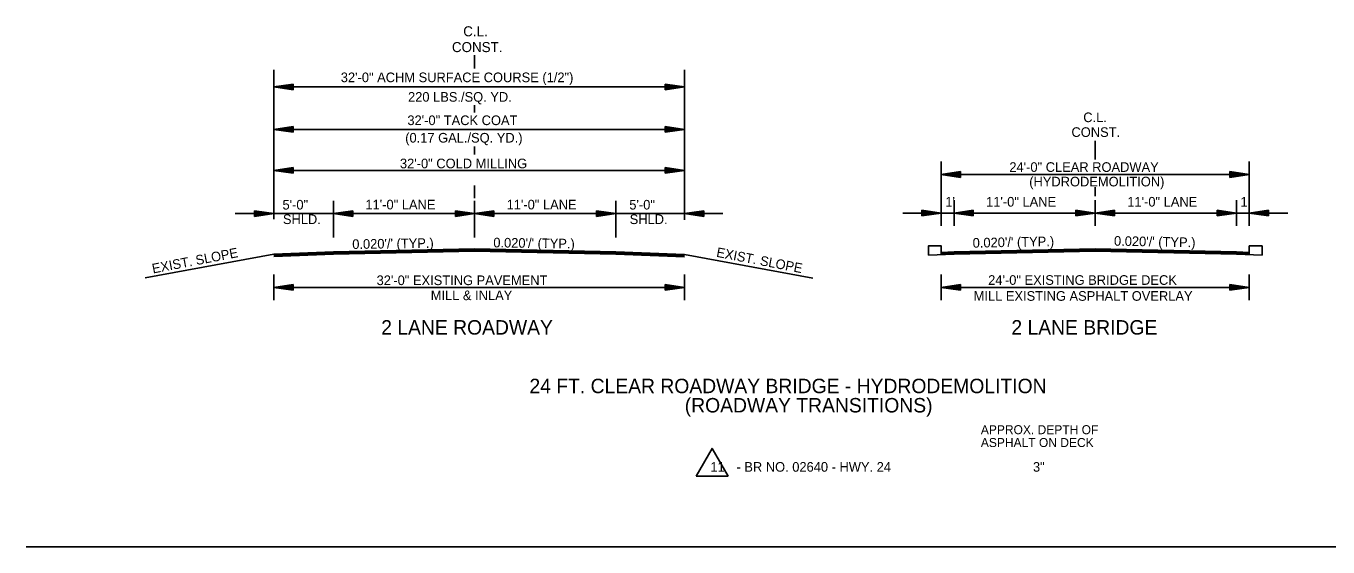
# Model space of a CAD drawing. Extents: x 549600 to 1930787, y -1955432 to 596640.
# Drawn here: x 551009 to 552023, y -1949914 to -1949509 of the extents above; entities that cross this region are included whole.
import ezdxf

# ---------------------------------------------------------------- set-up
doc = ezdxf.new("R2010")
doc.units = 0
for name, color, linetype in [('R_Border', 7, 'Continuous'), ('R_Border Notes', 7, 'Continuous'), ('S_AREA_CALC', 7, 'Continuous')]:
    doc.layers.add(name, color=color, linetype=linetype)

# ---------------------------------------------------------------- blocks, each defined once
blk = doc.blocks.new('ARROW')
at = {"layer": 'S_AREA_CALC'}
for p, q in [((-2, 0.3), (0, 0)), ((-2, 0.3), (-2, -0.3)), ((-2, 0.25), (-0.334, 0)), ((-2, 0.199), (-0.678, 0)), ((-2, 0.149), (-1.011, 0)), ((-2, 0.097), (-1.35, 0)), ((-2, 0.047), (-1.684, 0)), ((-2, -0.3), (0, 0)), ((-2, -0.098), (-1.35, 0)), ((-2, -0.199), (-0.678, 0)), ((-2, -0.25), (-0.334, 0)), ((-2, -0.149), (-1.011, 0)), ((-2, -0.047), (-1.684, 0))]:
    blk.add_line(p, q, dxfattribs=at)

msp = doc.modelspace()

# ---------------------------------------------------------------- linework, layer by layer
at = {"layer": 'R_Border'}
for p, q in [((551842, -1949598), (551842, -1949612.5)), ((551722, -1949614.2), (551722, -1949664.2)), ((551962, -1949614.2), (551962, -1949664.2)), ((551722, -1949624.2), (551962, -1949624.2)), ((551842, -1949634.2), (551842, -1949641.2)), ((551732, -1949644.2), (551732, -1949664.2)), ((551842, -1949644.2), (551842, -1949664.2)), ((551952, -1949644.2), (551952, -1949664.2)), ((551202, -1949654.6), (551172, -1949654.6)), ((551552, -1949654.6), (551522, -1949654.6)), ((551692, -1949654.2), (551992, -1949654.2)), ((551248.5, -1949684.4), (551202, -1949686.3)), ((551248.5, -1949684.7), (551202, -1949686.6)), ((551248.5, -1949685), (551202, -1949686.9)), ((551248.5, -1949685.3), (551202, -1949687.2)), ((551248.5, -1949685.6), (551202, -1949687.5)), ((551248.5, -1949685.9), (551202, -1949687.8)), ((551248.5, -1949686.1), (551202, -1949688)), ((551468.5, -1949684.4), (551522, -1949686.6)), ((551468.5, -1949684.7), (551522, -1949686.9)), ((551468.5, -1949685), (551522, -1949687.2)), ((551468.5, -1949685.3), (551522, -1949687.5)), ((551468.5, -1949685.6), (551522, -1949687.8)), ((551468.5, -1949685.9), (551522, -1949688.1)), ((551468.5, -1949686.1), (551522, -1949688.2)), ((551722, -1949702.1), (551722, -1949722.1)), ((551962, -1949702.1), (551962, -1949722.1)), ((551722, -1949712.1), (551962, -1949712.1)), ((551531.1, -1949858.9), (551555.9, -1949858.9)), ((551009, -1949914), (552070.2, -1949914))]:
    msp.add_line(p, q, dxfattribs=at)
for points in [[(551722, -1949686.3), (551722, -1949679.8), (551712, -1949679.8), (551712, -1949687)], [(551962, -1949687), (551962, -1949679.8), (551972, -1949679.8), (551972, -1949687)], [(551712, -1949687), (551732, -1949686.2), (551842, -1949684), (551952, -1949686.2), (551972, -1949687)], [(551722, -1949684.8), (551732, -1949684.4), (551842, -1949682.2), (551952, -1949684.4), (551962, -1949684.8)], [(551722, -1949685.1), (551732, -1949684.7), (551842, -1949682.5), (551952, -1949684.7), (551962, -1949685.1)], [(551722, -1949685.4), (551732, -1949685), (551842, -1949682.8), (551952, -1949685), (551962, -1949685.4)], [(551722, -1949685.7), (551732, -1949685.3), (551842, -1949683.1), (551952, -1949685.3), (551962, -1949685.7)], [(551722, -1949686), (551732, -1949685.6), (551842, -1949683.4), (551952, -1949685.6), (551962, -1949686)], [(551722, -1949686.3), (551732, -1949685.9), (551842, -1949683.7), (551952, -1949685.9), (551962, -1949686.3)], [(551555.9, -1949858.9), (551543.5, -1949837.4), (551531.1, -1949858.9)]]:
    msp.add_lwpolyline(points, dxfattribs=at)
at = {"layer": 'S_AREA_CALC'}
for p, q in [((551358.5, -1949541.7), (551358.5, -1949531.3)), ((551202, -1949659.1), (551202, -1949542.8)), ((551522, -1949659.6), (551522, -1949542.8)), ((551217, -1949553.9), (551202, -1949556.1)), ((551202, -1949556.1), (551522, -1949556.1)), ((551217, -1949558.4), (551202, -1949556.1)), ((551217, -1949554.3), (551204.5, -1949556.1)), ((551217, -1949558), (551204.5, -1949556.1)), ((551217, -1949554.6), (551207.1, -1949556.1)), ((551217, -1949557.6), (551207.1, -1949556.1)), ((551217, -1949555), (551209.6, -1949556.1)), ((551217, -1949557.3), (551209.6, -1949556.1)), ((551217, -1949555.4), (551212.1, -1949556.1)), ((551217, -1949556.9), (551212.1, -1949556.1)), ((551217, -1949555.8), (551214.6, -1949556.1)), ((551217, -1949556.5), (551214.6, -1949556.1)), ((551217, -1949558.4), (551217, -1949553.9)), ((551507, -1949553.9), (551522, -1949556.1)), ((551507, -1949553.9), (551507, -1949558.4)), ((551507, -1949554.3), (551519.5, -1949556.1)), ((551507, -1949554.6), (551516.9, -1949556.1)), ((551507, -1949555), (551514.4, -1949556.1)), ((551507, -1949555.4), (551511.9, -1949556.1)), ((551507, -1949555.8), (551509.4, -1949556.1)), ((551507, -1949558.4), (551522, -1949556.1)), ((551507, -1949556.9), (551511.9, -1949556.1)), ((551507, -1949557.6), (551516.9, -1949556.1)), ((551507, -1949558), (551519.5, -1949556.1)), ((551507, -1949557.3), (551514.4, -1949556.1)), ((551507, -1949556.5), (551509.4, -1949556.1)), ((551358.5, -1949575.9), (551358.5, -1949570.3)), ((551217, -1949586.9), (551202, -1949589.1)), ((551202, -1949589.1), (551522, -1949589.1)), ((551217, -1949591.4), (551202, -1949589.1)), ((551217, -1949587.2), (551204.5, -1949589.1)), ((551217, -1949591), (551204.5, -1949589.1)), ((551217, -1949587.6), (551207.1, -1949589.1)), ((551217, -1949590.6), (551207.1, -1949589.1)), ((551217, -1949588), (551209.6, -1949589.1)), ((551217, -1949590.2), (551209.6, -1949589.1)), ((551217, -1949588.4), (551212.1, -1949589.1)), ((551217, -1949589.8), (551212.1, -1949589.1)), ((551217, -1949588.8), (551214.6, -1949589.1)), ((551217, -1949589.5), (551214.6, -1949589.1)), ((551217, -1949591.4), (551217, -1949586.9)), ((551507, -1949586.9), (551522, -1949589.1)), ((551507, -1949586.9), (551507, -1949591.4)), ((551507, -1949587.2), (551519.5, -1949589.1)), ((551507, -1949587.6), (551516.9, -1949589.1)), ((551507, -1949588), (551514.4, -1949589.1)), ((551507, -1949588.4), (551511.9, -1949589.1)), ((551507, -1949588.8), (551509.4, -1949589.1)), ((551507, -1949591.4), (551522, -1949589.1)), ((551507, -1949589.8), (551511.9, -1949589.1)), ((551507, -1949590.6), (551516.9, -1949589.1)), ((551507, -1949591), (551519.5, -1949589.1)), ((551507, -1949590.2), (551514.4, -1949589.1)), ((551507, -1949589.5), (551509.4, -1949589.1)), ((551358.5, -1949608.8), (551358.5, -1949602.4)), ((551217, -1949618.8), (551202, -1949621.1)), ((551217, -1949619.2), (551204.5, -1949621.1)), ((551217, -1949619.6), (551207.1, -1949621.1)), ((551217, -1949620), (551209.6, -1949621.1)), ((551217, -1949620.3), (551212.1, -1949621.1)), ((551217, -1949620.7), (551214.6, -1949621.1)), ((551217, -1949623.3), (551217, -1949618.8)), ((551507, -1949618.8), (551522, -1949621.1)), ((551507, -1949618.8), (551507, -1949623.3)), ((551507, -1949619.2), (551519.5, -1949621.1)), ((551507, -1949619.6), (551516.9, -1949621.1)), ((551507, -1949620), (551514.4, -1949621.1)), ((551507, -1949620.4), (551511.9, -1949621.1)), ((551507, -1949620.7), (551509.4, -1949621.1)), ((551202, -1949621.1), (551522, -1949621.1)), ((551217, -1949623.3), (551202, -1949621.1)), ((551217, -1949623), (551204.5, -1949621.1)), ((551217, -1949622.6), (551207.1, -1949621.1)), ((551217, -1949622.2), (551209.6, -1949621.1)), ((551217, -1949621.8), (551212.1, -1949621.1)), ((551217, -1949621.4), (551214.6, -1949621.1)), ((551507, -1949623.3), (551522, -1949621.1)), ((551507, -1949621.8), (551511.9, -1949621.1)), ((551507, -1949622.6), (551516.9, -1949621.1)), ((551507, -1949623), (551519.5, -1949621.1)), ((551507, -1949622.2), (551514.4, -1949621.1)), ((551507, -1949621.4), (551509.4, -1949621.1)), ((551358.5, -1949642.6), (551358.5, -1949632.7)), ((551248.5, -1949673.3), (551248.5, -1949644.7)), ((551358.5, -1949673.3), (551358.5, -1949644.7)), ((551468.5, -1949673.3), (551468.5, -1949644.7)), ((551187, -1949652.4), (551202, -1949654.6)), ((551187, -1949652.4), (551187, -1949656.9)), ((551187, -1949652.7), (551199.5, -1949654.6)), ((551187, -1949653.1), (551196.9, -1949654.6)), ((551187, -1949653.5), (551194.4, -1949654.6)), ((551187, -1949653.9), (551191.9, -1949654.6)), ((551187, -1949654.3), (551189.4, -1949654.6)), ((551187, -1949656.9), (551202, -1949654.6)), ((551187, -1949655.4), (551191.9, -1949654.6)), ((551187, -1949656.1), (551196.9, -1949654.6)), ((551187, -1949656.5), (551199.5, -1949654.6)), ((551187, -1949655.7), (551194.4, -1949654.6)), ((551187, -1949655), (551189.4, -1949654.6)), ((551248.5, -1949654.6), (551202, -1949654.6)), ((551263.5, -1949652.4), (551248.5, -1949654.6)), ((551263.5, -1949656.9), (551248.5, -1949654.6)), ((551248.5, -1949654.6), (551358.5, -1949654.6)), ((551263.5, -1949652.7), (551251, -1949654.6)), ((551263.5, -1949656.5), (551251, -1949654.6)), ((551263.5, -1949653.1), (551253.6, -1949654.6)), ((551263.5, -1949656.1), (551253.6, -1949654.6)), ((551263.5, -1949653.5), (551256.1, -1949654.6)), ((551263.5, -1949655.7), (551256.1, -1949654.6)), ((551263.5, -1949653.9), (551258.6, -1949654.6)), ((551263.5, -1949655.3), (551258.6, -1949654.6)), ((551263.5, -1949654.3), (551261.1, -1949654.6)), ((551263.5, -1949655), (551261.1, -1949654.6)), ((551263.5, -1949656.9), (551263.5, -1949652.4)), ((551343.5, -1949652.4), (551358.5, -1949654.6)), ((551343.5, -1949652.4), (551343.5, -1949656.9)), ((551343.5, -1949652.7), (551356, -1949654.6)), ((551343.5, -1949653.1), (551353.4, -1949654.6)), ((551343.5, -1949653.5), (551350.9, -1949654.6)), ((551343.5, -1949653.9), (551348.3, -1949654.6)), ((551343.5, -1949654.3), (551345.8, -1949654.6)), ((551343.5, -1949656.9), (551358.5, -1949654.6)), ((551343.5, -1949655.4), (551348.3, -1949654.6)), ((551343.5, -1949656.1), (551353.4, -1949654.6)), ((551343.5, -1949656.5), (551356, -1949654.6)), ((551343.5, -1949655.7), (551350.9, -1949654.6)), ((551343.5, -1949655), (551345.8, -1949654.6)), ((551373.5, -1949652.4), (551358.5, -1949654.6)), ((551468.5, -1949654.6), (551358.5, -1949654.6)), ((551373.5, -1949656.9), (551358.5, -1949654.6)), ((551373.5, -1949652.7), (551361, -1949654.6)), ((551373.5, -1949656.5), (551361, -1949654.6)), ((551373.5, -1949653.1), (551363.6, -1949654.6)), ((551373.5, -1949656.1), (551363.6, -1949654.6)), ((551373.5, -1949653.5), (551366.1, -1949654.6)), ((551373.5, -1949655.7), (551366.1, -1949654.6)), ((551373.5, -1949653.9), (551368.6, -1949654.6)), ((551373.5, -1949655.4), (551368.6, -1949654.6)), ((551373.5, -1949654.3), (551371.1, -1949654.6)), ((551373.5, -1949655), (551371.1, -1949654.6)), ((551373.5, -1949652.4), (551373.5, -1949656.9)), ((551453.5, -1949652.4), (551468.5, -1949654.6)), ((551453.5, -1949656.9), (551453.5, -1949652.4)), ((551453.5, -1949652.7), (551466, -1949654.6)), ((551453.5, -1949653.1), (551463.4, -1949654.6)), ((551453.5, -1949653.5), (551460.9, -1949654.6)), ((551453.5, -1949653.9), (551458.3, -1949654.6)), ((551453.5, -1949654.3), (551455.8, -1949654.6)), ((551453.5, -1949656.9), (551468.5, -1949654.6)), ((551453.5, -1949655.3), (551458.3, -1949654.6)), ((551453.5, -1949656.1), (551463.4, -1949654.6)), ((551453.5, -1949656.5), (551466, -1949654.6)), ((551453.5, -1949655.7), (551460.9, -1949654.6)), ((551453.5, -1949655), (551455.8, -1949654.6)), ((551468.5, -1949654.6), (551522, -1949654.6)), ((551537, -1949652.4), (551522, -1949654.6)), ((551537, -1949656.9), (551522, -1949654.6)), ((551537, -1949652.7), (551524.5, -1949654.6)), ((551537, -1949656.5), (551524.5, -1949654.6)), ((551537, -1949653.1), (551527.1, -1949654.6)), ((551537, -1949656.1), (551527.1, -1949654.6)), ((551537, -1949653.5), (551529.6, -1949654.6)), ((551537, -1949655.7), (551529.6, -1949654.6)), ((551537, -1949653.9), (551532.1, -1949654.6)), ((551537, -1949655.4), (551532.1, -1949654.6)), ((551537, -1949654.3), (551534.6, -1949654.6)), ((551537, -1949655), (551534.6, -1949654.6)), ((551537, -1949652.4), (551537, -1949656.9)), ((551202, -1949686.3), (551101.9, -1949704.7)), ((551358.5, -1949682.2), (551248.5, -1949684.4)), ((551358.5, -1949682.5), (551248.5, -1949684.7)), ((551358.5, -1949682.8), (551248.5, -1949685)), ((551358.5, -1949683.1), (551248.5, -1949685.3)), ((551358.5, -1949683.4), (551248.5, -1949685.6)), ((551358.5, -1949683.7), (551248.5, -1949685.9)), ((551358.5, -1949683.9), (551248.5, -1949686.1)), ((551358.4, -1949683.7), (551468.5, -1949685.9)), ((551358.4, -1949683.9), (551468.5, -1949686.1)), ((551358.5, -1949682.2), (551468.5, -1949684.4)), ((551358.5, -1949682.5), (551468.5, -1949684.7)), ((551358.5, -1949682.8), (551468.5, -1949685)), ((551358.5, -1949683.1), (551468.5, -1949685.3)), ((551358.5, -1949683.4), (551468.5, -1949685.6)), ((551522, -1949686.6), (551622.1, -1949704.9)), ((551202, -1949702.1), (551202, -1949722.1)), ((551522, -1949702.1), (551522, -1949722.1)), ((551217, -1949709.8), (551202, -1949712.1)), ((551202, -1949712.1), (551522, -1949712.1)), ((551217, -1949714.3), (551202, -1949712.1)), ((551217, -1949710.2), (551204.5, -1949712.1)), ((551217, -1949714), (551204.5, -1949712.1)), ((551217, -1949710.6), (551207.1, -1949712.1)), ((551217, -1949713.6), (551207.1, -1949712.1)), ((551217, -1949711), (551209.6, -1949712.1)), ((551217, -1949713.2), (551209.6, -1949712.1)), ((551217, -1949711.3), (551212.1, -1949712.1)), ((551217, -1949712.8), (551212.1, -1949712.1)), ((551217, -1949711.7), (551214.6, -1949712.1)), ((551217, -1949712.4), (551214.6, -1949712.1)), ((551217, -1949714.3), (551217, -1949709.8)), ((551507, -1949709.8), (551522, -1949712.1)), ((551507, -1949709.8), (551507, -1949714.3)), ((551507, -1949710.2), (551519.5, -1949712.1)), ((551507, -1949710.6), (551516.9, -1949712.1)), ((551507, -1949711), (551514.4, -1949712.1)), ((551507, -1949711.4), (551511.9, -1949712.1)), ((551507, -1949711.7), (551509.4, -1949712.1)), ((551507, -1949714.3), (551522, -1949712.1)), ((551507, -1949712.8), (551511.9, -1949712.1)), ((551507, -1949713.6), (551516.9, -1949712.1)), ((551507, -1949714), (551519.5, -1949712.1)), ((551507, -1949713.2), (551514.4, -1949712.1)), ((551507, -1949712.4), (551509.4, -1949712.1))]:
    msp.add_line(p, q, dxfattribs=at)

# ---------------------------------------------------------------- block references
at = {"layer": 'R_Border', "xscale": 7.5, "yscale": 7.5, "rotation": 180}
for p in [(551722, -1949624.2), (551732, -1949654.2), (551842, -1949654.2), (551962, -1949654.2), (551722, -1949712.1)]:
    msp.add_blockref('ARROW', p, dxfattribs=at)
at = {"layer": 'R_Border', "xscale": 7.5, "yscale": 7.5}
for p in [(551962, -1949624.2), (551722, -1949654.2), (551842, -1949654.2), (551952, -1949654.2), (551962, -1949712.1)]:
    msp.add_blockref('ARROW', p, dxfattribs=at)

# ---------------------------------------------------------------- texts
at = {"layer": 'R_Border'}
for s, height, p in [('C.L.', 7.5, (551832.7, -1949583.5)), ('CONST.', 7.5, (551823.5, -1949595)), ('24\'-0" CLEAR ROADWAY', 7.5, (551775.1, -1949622.2)), ('(HYDRODEMOLITION)', 7.5, (551790.6, -1949633.5)), ("1'", 7.5, (551725.2, -1949649.2)), ('11\'-0" LANE', 7.5, (551757, -1949649.2)), ('11\'-0" LANE', 7.5, (551867, -1949649.2)), ("1'", 7.5, (551955.2, -1949649.2)), ('24\'-0" EXISTING BRIDGE DECK', 7.5, (551758.6, -1949710.1)), ('2 LANE ROADWAY', 11.25, (551285.7, -1949748.8)), ('2 LANE BRIDGE', 11.25, (551776.7, -1949748.8)), ('24 FT. CLEAR ROADWAY BRIDGE - HYDRODEMOLITION', 11.25, (551401.2, -1949794.4)), ('(ROADWAY TRANSITIONS)', 11.25, (551522.2, -1949809.4)), ('11', 7.5, (551542.2, -1949855.5)), ('- BR NO. 02640 - HWY. 24', 7.5, (551562.5, -1949855.5)), ('3"', 7.5, (551793.5, -1949855.5))]:
    msp.add_text(s, height=height, dxfattribs=at).set_placement(p)
for rotation, p in [(1.1458, (551746.6, -1949681.2)), (358.8542, (551856.6, -1949679.6))]:
    msp.add_text("0.020'/' (TYP.)", height=7.5, rotation=rotation, dxfattribs=at).set_placement(p)
at = {"layer": 'R_Border Notes'}
for s, p in [('APPROX. DEPTH OF', (551752.9, -1949826.3)), ('ASPHALT ON DECK', (551752.9, -1949836.3))]:
    msp.add_text(s, height=7, dxfattribs=at).set_placement(p)
at = {"layer": 'S_AREA_CALC'}
for s, height, p in [('C.L.', 7.8, (551349.6, -1949516.7)), ('CONST.', 7.8, (551340.8, -1949529)), ('32\'-0" ACHM SURFACE COURSE (1/2")', 7.5, (551254.2, -1949552.4)), ('220 LBS./SQ. YD. ', 7.5, (551306.6, -1949567.6)), ('32\'-0" TACK COAT', 7.5, (551306.1, -1949585.8)), ('(0.17 GAL./SQ. YD.)', 7.5, (551304.4, -1949599.4)), ('32\'-0" COLD MILLING ', 7.5, (551300.3, -1949619.4)), (' 5\'-0"', 7.5, (551206, -1949651.5)), ('11\'-0" LANE', 7.5, (551273.4, -1949651.4)), ('11\'-0" LANE', 7.5, (551383.4, -1949651.4)), (' 5\'-0"', 7.5, (551476.2, -1949651.5)), ('SHLD.', 7.5, (551209.1, -1949662.8)), ('SHLD.', 7.5, (551479.3, -1949662.8)), ('32\'-0" EXISTING PAVEMENT', 7.5, (551282.1, -1949710.3)), ('MILL & INLAY', 7.5, (551324.3, -1949722)), ('MILL EXISTING ASPHALT OVERLAY', 7.5, (551747.3, -1949722.5))]:
    msp.add_text(s, height=height, dxfattribs=at).set_placement(p)
for s, rotation, p in [('EXIST. SLOPE', 10.8829, (551107.9, -1949701.3)), ("0.020'/' (TYP.)", 0.8719, (551263.2, -1949682.2)), ("0.020'/' (TYP.)", 359.1281, (551373, -1949680.9)), ('EXIST. SLOPE', 349.1171, (551546.4, -1949688.2))]:
    msp.add_text(s, height=7.5, rotation=rotation, dxfattribs=at).set_placement(p)

doc.saveas('drawing.dxf')
